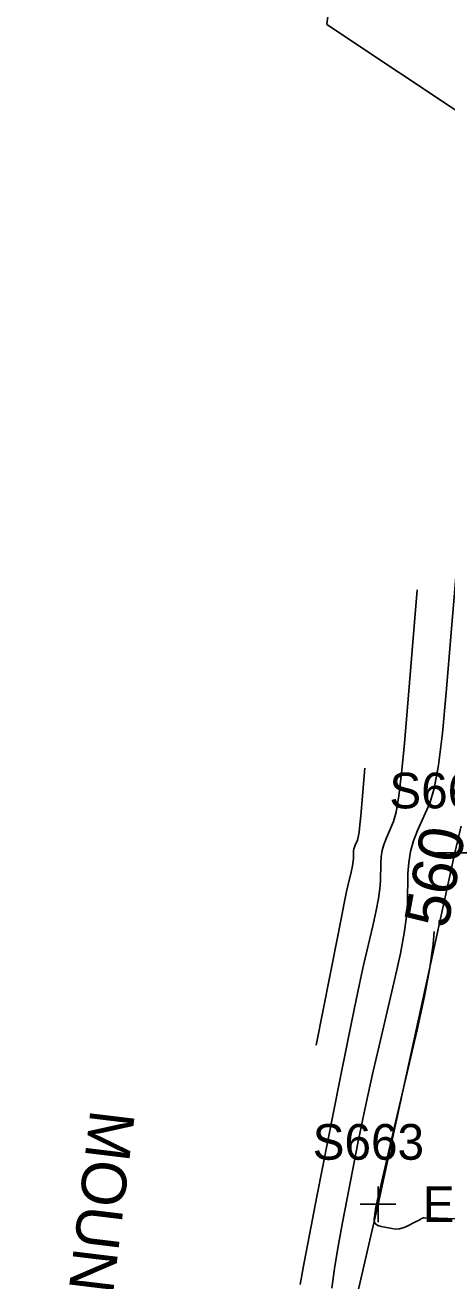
# Model space of a CAD drawing. Extents: x 1724534 to 1727318, y 657156 to 660047.
# Drawn here: x 1725345.2 to 1725392.5, y 658800.5 to 658941.3 of the extents above; entities that cross this region are included whole.
import ezdxf

# ---------------------------------------------------------------- set-up
doc = ezdxf.new("R2010")
doc.units = 0
for name, color, linetype in [('SURVEY - CONTOURS - Index with Text', 7, 'Continuous'), ('SURVEY - CONTOURS - Intermediate with optional Text', 7, 'Continuous'), ('SURVEY - DRAINAGE - Storm Sewer Text', 7, 'Continuous'), ('SURVEY - NON-TRANSPORTATION - Features', 7, 'Continuous'), ('SURVEY - NON-TRANSPORTATION - Features - Points - Elevations', 7, 'Continuous'), ('SURVEY - NON-TRANSPORTATION - Features - Points - Locators', 7, 'Continuous'), ('SURVEY - NON-TRANSPORTATION - Features - Points - Numbers', 7, 'Continuous'), ('SURVEY - TRANSPORTATION - Features Text', 7, 'Continuous')]:
    doc.layers.add(name, color=color, linetype=linetype)

msp = doc.modelspace()

# ---------------------------------------------------------------- linework, layer by layer
at = {"layer": 'SURVEY - CONTOURS - Index with Text'}
msp.add_lwpolyline([(1725391.05, 658839.69), (1725390.95, 658838.27), (1725390.57, 658835.64), (1725389.97, 658832.44), (1725389.13, 658828.67), (1725386.6, 658817.84), (1725385.76, 658814.27), (1725385.16, 658811.69), (1725384.79, 658810.09), (1725384.65, 658809.47), (1725384.58, 658809.13), (1725384.55, 658808.98), (1725384.52, 658808.79), (1725384.48, 658808.54), (1725384.44, 658808.26), (1725384.32, 658807.43), (1725384.33, 658807.15), (1725384.47, 658806.92), (1725384.73, 658806.75), (1725385.11, 658806.63), (1725386.28, 658806.4), (1725386.71, 658806.34), (1725387.14, 658806.36), (1725387.55, 658806.46), (1725387.95, 658806.63), (1725389.01, 658807.17), (1725389.35, 658807.35), (1725389.6, 658807.48), (1725389.75, 658807.55), (1725389.81, 658807.58), (1725389.92, 658807.58), (1725390.24, 658807.57), (1725390.75, 658807.56), (1725391.48, 658807.54), (1725393.69, 658807.48)], dxfattribs=at)
at = {"layer": 'SURVEY - CONTOURS - Intermediate with optional Text'}
for points in [[(1725393.87, 658884.35), (1725392.4, 658866.49), (1725391.97, 658861.93), (1725391.52, 658858.35), (1725391.05, 658855.74), (1725390.55, 658854.1), (1725389.18, 658851.02), (1725388.73, 658849.85), (1725388.4, 658848.66), (1725388.2, 658847.44), (1725388.11, 658846.2), (1725388.06, 658842.85), (1725387.95, 658841.39), (1725387.69, 658839.52), (1725387.26, 658837.25), (1725386.66, 658834.57), (1725384.86, 658826.88), (1725384.21, 658824.05), (1725383.61, 658821.32), (1725383.05, 658818.69), (1725382.54, 658816.16), (1725381.24, 658809.56), (1725380.77, 658807.09), (1725380.33, 658804.62), (1725379.92, 658802.16), (1725379.55, 658799.7)], [(1725389.13, 658878.01), (1725387.71, 658860.78), (1725387.4, 658857.46), (1725387.1, 658854.9), (1725386.8, 658853.08), (1725386.49, 658852.03), (1725385.69, 658850.2), (1725385.42, 658849.51), (1725385.22, 658848.81), (1725385.1, 658848.08), (1725385.05, 658847.35), (1725385.02, 658845.37), (1725384.96, 658844.5), (1725384.8, 658843.4), (1725384.55, 658842.05), (1725384.19, 658840.47), (1725383.13, 658835.92), (1725382.66, 658833.82), (1725382.06, 658830.94), (1725381.31, 658827.29), (1725380.43, 658822.86), (1725377.9, 658809.99), (1725377.06, 658805.68), (1725376.43, 658802.4), (1725376.01, 658800.13)], [(1725377.82, 658826.97), (1725380.15, 658838.82), (1725380.6, 658841.1), (1725380.96, 658842.89), (1725381.23, 658844.17), (1725381.4, 658844.95), (1725381.73, 658846.36), (1725381.84, 658846.86), (1725381.92, 658847.27), (1725381.96, 658847.62), (1725381.98, 658847.88), (1725381.99, 658848.5), (1725382.01, 658848.73), (1725382.05, 658848.95), (1725382.11, 658849.17), (1725382.19, 658849.39), (1725382.44, 658849.95), (1725382.53, 658850.28), (1725382.63, 658850.84), (1725382.72, 658851.64), (1725382.82, 658852.67), (1725383.26, 658858.01)]]:
    msp.add_lwpolyline(points, dxfattribs=at)
at = {"layer": 'SURVEY - DRAINAGE - Storm Sewer Text'}
msp.add_lwpolyline([(1725419.1, 658914.75), (1725378.99, 658941.4), (1725386.06, 658999.74)], dxfattribs=at)
at = {"layer": 'SURVEY - NON-TRANSPORTATION - Features'}
msp.add_lwpolyline([(1725357.68, 658691.93), (1725363.17, 658711.31), (1725369.34, 658739.88), (1725375.28, 658769.31), (1725379.12, 658784.74), (1725384.76, 658809.11), (1725393.36, 658848.5), (1725405.65, 658900.8), (1725418.14, 658956.87), (1725428.71, 659003.82), (1725429.42, 659007.15)], dxfattribs=at)
at = {"layer": 'SURVEY - NON-TRANSPORTATION - Features - Points - Locators'}
for p, q in [((1725395.36, 658848.5), (1725391.36, 658848.5)), ((1725384.76, 658811.11), (1725384.76, 658807.11)), ((1725386.76, 658809.11), (1725382.76, 658809.11))]:
    msp.add_line(p, q, dxfattribs=at)

# ---------------------------------------------------------------- texts
at = {"layer": 'SURVEY - CONTOURS - Index with Text'}
msp.add_text('560', height=5, rotation=79.4863, dxfattribs=at).set_placement((1725392.55, 658839.9))
at = {"layer": 'SURVEY - NON-TRANSPORTATION - Features - Points - Elevations'}
msp.add_text('EL-559.95', height=4, dxfattribs=at).set_placement((1725389.76, 658807.11))
at = {"layer": 'SURVEY - NON-TRANSPORTATION - Features - Points - Numbers'}
for s, p in [('S664', (1725386.02, 658853.5)), ('S663', (1725377.42, 658814.11))]:
    msp.add_text(s, height=4, dxfattribs=at).set_placement(p)
at = {"layer": 'SURVEY - TRANSPORTATION - Features Text'}
msp.add_text('MOUNTABLE CURB', height=5, rotation=263.0935, dxfattribs=at).set_placement((1725352.52, 658819.86))

doc.saveas('drawing.dxf')
